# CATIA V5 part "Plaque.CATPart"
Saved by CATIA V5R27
Part number: Plaque
Bounding box of the stored display mesh (mm): x 38.1 to 345.44, y -38.1 to 342.9, z 0 to 6.35
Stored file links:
  \\triton.meca.polymtl.ca\usagers\zaoue\profiles\Desktop\varm_ass\plaque moteur\Plaque.CATPart
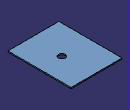
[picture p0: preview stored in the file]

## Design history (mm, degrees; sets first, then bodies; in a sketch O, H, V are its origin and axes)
Body1 (main body)
  Sketch1 on xy-plane, origin (0, 0, 0), H (1, 0, 0), V (0, 1, 0)
    line L1 (0, 0) -> (0, 304.8)
    line L2 (0, 304.8) -> (38.1, 304.8)
    line L3 (38.1, 304.8) -> (38.1, 342.9)
    line L4 (38.1, 342.9) -> (345.44, 342.9)
    line L5 (345.44, 342.9) -> (345.44, 304.8)
    point P5 (345.44, 304.8)
    line L6 (345.44, 304.8) -> (383.54, 304.8)
    line L7 (383.54, 304.8) -> (383.54, 0)
    point P7 (383.54, 0)
    line L8 (383.54, 0) -> (345.44, 0)
    point P8 (345.44, 0)
    line L9 (345.44, 0) -> (345.44, -38.1)
    line L10 (345.44, -38.1) -> (38.1, -38.1)
    point P10 (38.1, -38.1)
    line L11 (38.1, -38.1) -> (38.1, 0)
    point P11 (38.1, 0)
    line L12 (38.1, 0) -> (0, 0)
    length L12 = 38.1
    length L11 = 38.1
    length L10 = 307.34
    length L3 = 38.1
    length L6 = 38.1
    length L1 = 304.8
    vertical: L1 V, L3 V, L5 V, L7 V, L9 V, L11 V
    horizontal: L2 H, L4 H, L6 H, L8 H, L10 H, L12 H
    coincidence: P5 L2, P7 H, P8 L5, P10 L3, P11 H
  Pad1: profile Sketch1, direction (0, 0, 1), length 6.35
  DatumCurve1
  DatumCurve2
  Sketch2 on end face of Pad1, origin (0, 0, 6.35), H (1, 0, 0), V (0, 1, 0)
    line L1 (38.1, 342.9) -> (345.44, 342.9)
    line L2 (345.44, 342.9) -> (345.44, -38.1)
    line L3 (345.44, -38.1) -> (38.1, -38.1)
    line L4 (38.1, -38.1) -> (38.1, 342.9)
    reference projected line E1 (345.44, 342.9) -> (38.1, 342.9) from edge [face of Pad1 from Sketch1.L4 | end face of Pad1]
    reference projected line E2 (38.1, -38.1) -> (345.44, -38.1) from edge [face of Pad1 from Sketch1.L10 | end face of Pad1]
    reference projected line E3 (38.1, 342.9) -> (38.1, 309.626) from edge of DatumCurve2
    reference projected line E4 (345.44, -38.1) -> (345.44, 0) from edge [face of Pad1 from Sketch1.L9 | end face of Pad1]
    horizontal: L1 H, L3 H
    vertical: L2 V, L4 V
    coincidence: L1 E1, E2 L3, L4 E3, L2 E4
  Pocket1: profile Sketch2, direction (0, 0, -1), through (limit type 3), outer side
  Sketch3 on end face of Pad1, origin (204.3684, 157.1181, 6.35), H (1, 0, 0), V (0, 1, 0)
    point P1 (6.0716, -4.7181)
    reference projected line E1 (141.0716, -157.1181) -> (141.0716, -195.2181) from edge [face of Pad1 | end face of Pad1]
    reference projected line E3 (141.0716, 185.7819) -> (-166.2684, 185.7819) from edge [face of Pad1 from Sketch1.L4 | end face of Pad1]
    reference intersected line E4 (141.0716, -195.2181) -> (-166.2684, -195.2181) from face of Pad1 from Sketch1.L10
    distance P1 E1 = 135
    distance P1 E3 = 190.5 (reference)
    distance E4 P1 = 190.5 {= Sketch3.distance(P1 E3)}
  Hole1: placed by Sketch3, at (210.44, 152.4, 6.35) direction (0, 0, -1), diameter 40, through (limit type 3)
